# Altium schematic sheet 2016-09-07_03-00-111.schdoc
size 252 x 116 mm; SheetNumber: 1; SheetTotal: 1
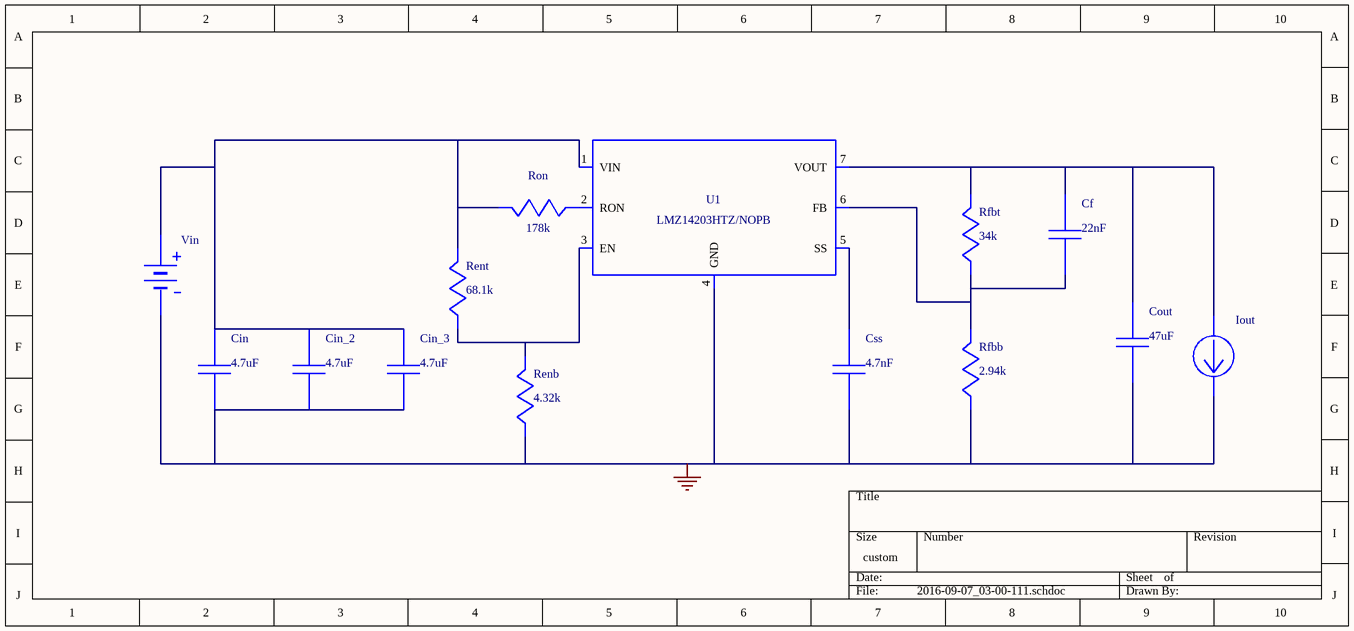
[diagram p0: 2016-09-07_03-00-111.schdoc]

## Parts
Cf  value 22nF  (hidden comment: CC0805KRX7R9BB223)
Cin  value 4.7uF  (hidden comment: GRM31CR71H475KA12L)
Cin_2  value 4.7uF  (hidden comment: GRM31CR71H475KA12L)
Cin_3  value 4.7uF  (hidden comment: GRM31CR71H475KA12L)
Cout  value 47uF  (hidden comment: GRM32ER61C476ME15L)
Css  value 4.7nF  (hidden comment: CC0805KRX7R9BB472)
Iout  WB_CURRENT_LOAD  (value not drawn)
Renb  value 4.32k  (hidden comment: ERJ-6ENF4321V)
Rent  value 68.1k  (hidden comment: ERJ-6ENF6812V)
Rfbb  value 2.94k  (hidden comment: ERJ-6ENF2941V)
Rfbt  value 34k  (hidden comment: ERJ-6ENF3402V)
Ron  value 178k  (hidden comment: ERJ-6ENF1783V)
U1  LMZ14203HTZ/NOPB
Vin  WB_BATTERY  (value not drawn)

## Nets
0: Cin.2 Cin_2.2 Cin_3.2 Cout.2 Css.2 Iout.2(-) Renb.2 Rfbb.2 U1.4(GND) U1.8(EP) Vin.2(-)
NetCf_1: Cf.1 Cout.1 Iout.1(+) Rfbt.1 U1.7(VOUT)
NetCf_2: Cf.2 Rfbb.1 Rfbt.2 U1.6(FB)
NetCin_1: Cin.1 Cin_2.1 Cin_3.1 Rent.1 Ron.1 U1.1(VIN) Vin.1(+)
NetCss_1: Css.1 U1.5(SS)
NetRenb_1: Renb.1 Rent.2 U1.3(EN)
NetRon_2: Ron.2 U1.2(RON)

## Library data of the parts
Cf = CC0805KRX7R9BB223: CC0805KRX7R9BB22; Manufacturer Name: Yageo America
Cin Cin_2 Cin_3 = GRM31CR71H475KA12L: GRM31CR71H475KA1; Manufacturer Name: MuRata
Cout = GRM32ER61C476ME15L: GRM32ER61C476ME1; Manufacturer Name: MuRata
Css = CC0805KRX7R9BB472: CC0805KRX7R9BB47; Manufacturer Name: Yageo America
Renb = ERJ-6ENF4321V: Manufacturer Name: Panasonic
Rent = ERJ-6ENF6812V: Manufacturer Name: Panasonic
Rfbb = ERJ-6ENF2941V: Manufacturer Name: Panasonic
Rfbt = ERJ-6ENF3402V: Manufacturer Name: Panasonic
Ron = ERJ-6ENF1783V: Manufacturer Name: Panasonic
U1 = LMZ14203HTZ/NOPB: Manufacturer Name: Texas Instruments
